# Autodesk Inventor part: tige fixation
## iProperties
Created: 2002-09
Part Number: tige fixation
Material: Par défaut
Document SubType Name: Modélisation
Designer: Fmarro
Control State: 0
Master: False
Checked Out: False
Shininess: 15.0
Length Units: 11269
Angle Units: 11279
Time Units: 11290
Mass Units: 11283
Length Display Precision: 3
Angle Display Precision: 2
Density: 0.0
Volumn: 0.0
Area: 0.0
PropertySet Name: Model Information
Author: Fmarro
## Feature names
1. Extrusion1
